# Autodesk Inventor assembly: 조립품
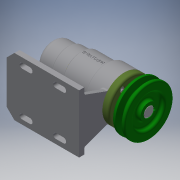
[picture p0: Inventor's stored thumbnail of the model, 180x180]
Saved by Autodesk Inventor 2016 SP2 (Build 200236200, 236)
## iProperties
Created: 2017-09
Part Number: 조립품
Document SubType Name: Assembly
Designer: Administrator
Author: Administrator
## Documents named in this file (12)
- D:\atc\470907V1007\조립품.iam
- D:\atc\470907V1007\본체.ipt
- D:\atc\470907V1007\베어링 51202.ipt
- D:\atc\470907V1007\어댑터슬리브.ipt
- D:\atc\470907V1007\베어링 6004.ipt
- D:\atc\470907V1007\커버.ipt
- D:\atc\470907V1007\볼트 M4 x 12.ipt
- D:\atc\470907V1007\V벨트풀리.ipt
- D:\atc\470907V1007\멈춤나사 M3x8.ipt
- D:\atc\470907V1007\오일 실 20x35x7.ipt
- D:\atc\470907V1007\축.ipt
- D:\atc\470907V1007\키 5 x 5 x 16.ipt
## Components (1 placed, 1 different names)
1. V벨트풀리:1
